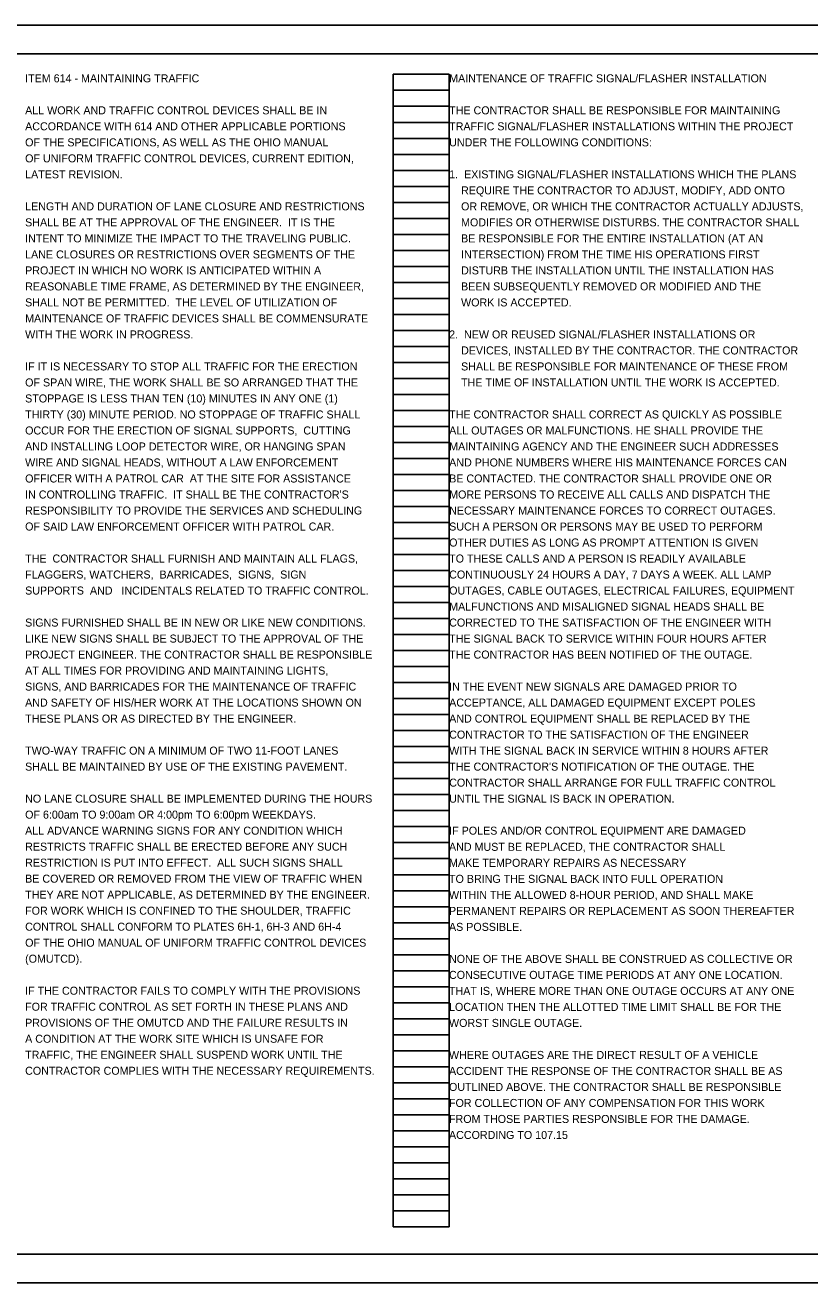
# Model space of a CAD drawing. Extents: x -7.3 to 34, y 0 to 22.
# Drawn here: x 2.4 to 16.13, y 0 to 22 of the extents above; entities that cross this region are included whole.
import ezdxf

# ---------------------------------------------------------------- set-up
doc = ezdxf.new("R2010")
doc.units = 0
for name, color, linetype in [('SH_Border', 7, 'Continuous'), ('SH_Cut_Line', 7, 'Continuous'), ('SH_Data', 7, 'Continuous'), ('SH_Text', 7, 'Continuous')]:
    doc.layers.add(name, color=color, linetype=linetype)

msp = doc.modelspace()

# ---------------------------------------------------------------- linework, layer by layer
at = {"layer": 'SH_Border'}
msp.add_lwpolyline([(1.5, 21.5), (33.5, 21.5), (33.5, 0.5), (1.5, 0.5)], close=True, dxfattribs=at)
at = {"layer": 'SH_Cut_Line'}
msp.add_lwpolyline([(0, 0), (34, 0), (34, 22), (0, 22)], close=True, dxfattribs=at)
at = {"layer": 'SH_Data'}
for p, q in [((8.84, 0.98), (8.84, 21.14)), ((8.84, 21.14), (9.82, 21.14)), ((9.82, 0.98), (9.82, 21.14)), ((8.84, 20.86), (9.82, 20.86)), ((8.84, 20.58), (9.82, 20.58)), ((8.84, 20.3), (9.82, 20.3)), ((8.84, 20.02), (9.82, 20.02)), ((8.84, 19.74), (9.82, 19.74)), ((8.84, 19.46), (9.82, 19.46)), ((8.84, 19.18), (9.82, 19.18)), ((8.84, 18.9), (9.82, 18.9)), ((8.84, 18.62), (9.82, 18.62)), ((8.84, 18.34), (9.82, 18.34)), ((8.84, 18.06), (9.82, 18.06)), ((8.84, 17.78), (9.82, 17.78)), ((8.84, 17.5), (9.82, 17.5)), ((8.84, 17.22), (9.82, 17.22)), ((8.84, 16.94), (9.82, 16.94)), ((8.84, 16.66), (9.82, 16.66)), ((8.84, 16.38), (9.82, 16.38)), ((8.84, 16.1), (9.82, 16.1)), ((8.84, 15.82), (9.82, 15.82)), ((8.84, 15.54), (9.82, 15.54)), ((8.84, 15.26), (9.82, 15.26)), ((8.84, 14.98), (9.82, 14.98)), ((8.84, 14.7), (9.82, 14.7)), ((8.84, 14.42), (9.82, 14.42)), ((8.84, 14.14), (9.82, 14.14)), ((8.84, 13.86), (9.82, 13.86)), ((8.84, 13.58), (9.82, 13.58)), ((8.84, 13.3), (9.82, 13.3)), ((8.84, 13.02), (9.82, 13.02)), ((8.84, 12.74), (9.82, 12.74)), ((8.84, 12.46), (9.82, 12.46)), ((8.84, 12.18), (9.82, 12.18)), ((8.84, 11.9), (9.82, 11.9)), ((8.84, 11.62), (9.82, 11.62)), ((8.84, 11.34), (9.82, 11.34)), ((8.84, 11.06), (9.82, 11.06)), ((8.84, 10.78), (9.82, 10.78)), ((8.84, 10.5), (9.82, 10.5)), ((8.84, 10.22), (9.82, 10.22)), ((8.84, 9.94), (9.82, 9.94)), ((8.84, 9.66), (9.82, 9.66)), ((8.84, 9.38), (9.82, 9.38)), ((8.84, 9.1), (9.82, 9.1)), ((8.84, 8.82), (9.82, 8.82)), ((8.84, 8.54), (9.82, 8.54)), ((8.84, 8.26), (9.82, 8.26)), ((8.84, 7.98), (9.82, 7.98)), ((8.84, 7.7), (9.82, 7.7)), ((8.84, 7.42), (9.82, 7.42)), ((8.84, 7.14), (9.82, 7.14)), ((8.84, 6.86), (9.82, 6.86)), ((8.84, 6.58), (9.82, 6.58)), ((8.84, 6.3), (9.82, 6.3)), ((8.84, 6.02), (9.82, 6.02)), ((8.84, 5.74), (9.82, 5.74)), ((8.84, 5.46), (9.82, 5.46)), ((8.84, 5.18), (9.82, 5.18)), ((8.84, 4.9), (9.82, 4.9)), ((8.84, 4.62), (9.82, 4.62)), ((8.84, 4.34), (9.82, 4.34)), ((8.84, 4.06), (9.82, 4.06)), ((8.84, 3.78), (9.82, 3.78)), ((8.84, 3.5), (9.82, 3.5)), ((8.84, 3.22), (9.82, 3.22)), ((8.84, 2.94), (9.82, 2.94)), ((8.84, 2.66), (9.82, 2.66)), ((8.84, 2.38), (9.82, 2.38)), ((8.84, 2.1), (9.82, 2.1)), ((8.84, 1.82), (9.82, 1.82)), ((8.84, 1.54), (9.82, 1.54)), ((8.84, 1.26), (9.82, 1.26)), ((8.84, 0.98), (9.82, 0.98))]:
    msp.add_line(p, q, dxfattribs=at)

# ---------------------------------------------------------------- texts
at = {"layer": 'SH_Text'}
for s, p in [('ITEM 614 - MAINTAINING TRAFFIC', (2.4, 21)), ('MAINTENANCE OF TRAFFIC SIGNAL/FLASHER INSTALLATION', (9.82, 21)), ('ALL WORK AND TRAFFIC CONTROL DEVICES SHALL BE IN', (2.4, 20.44)), ('THE CONTRACTOR SHALL BE RESPONSIBLE FOR MAINTAINING', (9.82, 20.44)), ('ACCORDANCE WITH 614 AND OTHER APPLICABLE PORTIONS', (2.4, 20.16)), ('TRAFFIC SIGNAL/FLASHER INSTALLATIONS WITHIN THE PROJECT', (9.82, 20.16)), ('OF THE SPECIFICATIONS, AS WELL AS THE OHIO MANUAL', (2.4, 19.88)), ('UNDER THE FOLLOWING CONDITIONS:', (9.82, 19.88)), ('OF UNIFORM TRAFFIC CONTROL DEVICES, CURRENT EDITION,', (2.4, 19.6)), ('LATEST REVISION.', (2.4, 19.32)), ('1.  EXISTING SIGNAL/FLASHER INSTALLATIONS WHICH THE PLANS', (9.82, 19.32)), ('    REQUIRE THE CONTRACTOR TO ADJUST, MODIFY, ADD ONTO', (9.82, 19.04)), ('LENGTH AND DURATION OF LANE CLOSURE AND RESTRICTIONS', (2.4, 18.76)), ('    OR REMOVE, OR WHICH THE CONTRACTOR ACTUALLY ADJUSTS,', (9.82, 18.76)), ('SHALL BE AT THE APPROVAL OF THE ENGINEER.  IT IS THE', (2.4, 18.48)), ('    MODIFIES OR OTHERWISE DISTURBS. THE CONTRACTOR SHALL', (9.82, 18.48)), ('INTENT TO MINIMIZE THE IMPACT TO THE TRAVELING PUBLIC.', (2.4, 18.2)), ('    BE RESPONSIBLE FOR THE ENTIRE INSTALLATION (AT AN', (9.82, 18.2)), ('LANE CLOSURES OR RESTRICTIONS OVER SEGMENTS OF THE', (2.4, 17.92)), ('    INTERSECTION) FROM THE TIME HIS OPERATIONS FIRST', (9.82, 17.92)), ('PROJECT IN WHICH NO WORK IS ANTICIPATED WITHIN A', (2.4, 17.64)), ('    DISTURB THE INSTALLATION UNTIL THE INSTALLATION HAS', (9.82, 17.64)), ('REASONABLE TIME FRAME, AS DETERMINED BY THE ENGINEER,', (2.4, 17.36)), ('    BEEN SUBSEQUENTLY REMOVED OR MODIFIED AND THE', (9.82, 17.36)), ('SHALL NOT BE PERMITTED.  THE LEVEL OF UTILIZATION OF', (2.4, 17.08)), ('    WORK IS ACCEPTED.', (9.82, 17.08)), ('MAINTENANCE OF TRAFFIC DEVICES SHALL BE COMMENSURATE', (2.4, 16.8)), ('WITH THE WORK IN PROGRESS.', (2.4, 16.52)), ('2.  NEW OR REUSED SIGNAL/FLASHER INSTALLATIONS OR', (9.82, 16.52)), ('    DEVICES, INSTALLED BY THE CONTRACTOR. THE CONTRACTOR', (9.82, 16.24)), ('IF IT IS NECESSARY TO STOP ALL TRAFFIC FOR THE ERECTION', (2.4, 15.96)), ('    SHALL BE RESPONSIBLE FOR MAINTENANCE OF THESE FROM', (9.82, 15.96)), ('OF SPAN WIRE, THE WORK SHALL BE SO ARRANGED THAT THE', (2.4, 15.68)), ('    THE TIME OF INSTALLATION UNTIL THE WORK IS ACCEPTED.', (9.82, 15.68)), ('STOPPAGE IS LESS THAN TEN (10) MINUTES IN ANY ONE (1)', (2.4, 15.4)), ('THIRTY (30) MINUTE PERIOD. NO STOPPAGE OF TRAFFIC SHALL', (2.4, 15.12)), ('THE CONTRACTOR SHALL CORRECT AS QUICKLY AS POSSIBLE', (9.82, 15.12)), ('OCCUR FOR THE ERECTION OF SIGNAL SUPPORTS,  CUTTING', (2.4, 14.84)), ('ALL OUTAGES OR MALFUNCTIONS. HE SHALL PROVIDE THE', (9.82, 14.84)), ('AND INSTALLING LOOP DETECTOR WIRE, OR HANGING SPAN', (2.4, 14.56)), ('MAINTAINING AGENCY AND THE ENGINEER SUCH ADDRESSES', (9.82, 14.56)), ('WIRE AND SIGNAL HEADS, WITHOUT A LAW ENFORCEMENT', (2.4, 14.28)), ('AND PHONE NUMBERS WHERE HIS MAINTENANCE FORCES CAN', (9.82, 14.28)), ('OFFICER WITH A PATROL CAR  AT THE SITE FOR ASSISTANCE', (2.4, 14)), ('BE CONTACTED. THE CONTRACTOR SHALL PROVIDE ONE OR', (9.82, 14)), ("IN CONTROLLING TRAFFIC.  IT SHALL BE THE CONTRACTOR'S", (2.4, 13.72)), ('MORE PERSONS TO RECEIVE ALL CALLS AND DISPATCH THE', (9.82, 13.72)), ('RESPONSIBILITY TO PROVIDE THE SERVICES AND SCHEDULING', (2.4, 13.44)), ('NECESSARY MAINTENANCE FORCES TO CORRECT OUTAGES.', (9.82, 13.44)), ('OF SAID LAW ENFORCEMENT OFFICER WITH PATROL CAR.', (2.4, 13.16)), ('SUCH A PERSON OR PERSONS MAY BE USED TO PERFORM', (9.82, 13.16)), ('OTHER DUTIES AS LONG AS PROMPT ATTENTION IS GIVEN', (9.82, 12.88)), ('THE  CONTRACTOR SHALL FURNISH AND MAINTAIN ALL FLAGS,', (2.4, 12.6)), ('TO THESE CALLS AND A PERSON IS READILY AVAILABLE', (9.82, 12.6)), ('FLAGGERS, WATCHERS,  BARRICADES,  SIGNS,  SIGN', (2.4, 12.32)), ('CONTINUOUSLY 24 HOURS A DAY, 7 DAYS A WEEK. ALL LAMP', (9.82, 12.32)), ('SUPPORTS  AND   INCIDENTALS RELATED TO TRAFFIC CONTROL.', (2.4, 12.04)), ('OUTAGES, CABLE OUTAGES, ELECTRICAL FAILURES, EQUIPMENT', (9.82, 12.04)), ('MALFUNCTIONS AND MISALIGNED SIGNAL HEADS SHALL BE', (9.82, 11.76)), ('SIGNS FURNISHED SHALL BE IN NEW OR LIKE NEW CONDITIONS.', (2.4, 11.48)), ('CORRECTED TO THE SATISFACTION OF THE ENGINEER WITH', (9.82, 11.48)), ('LIKE NEW SIGNS SHALL BE SUBJECT TO THE APPROVAL OF THE', (2.4, 11.2)), ('THE SIGNAL BACK TO SERVICE WITHIN FOUR HOURS AFTER', (9.82, 11.2)), ('PROJECT ENGINEER. THE CONTRACTOR SHALL BE RESPONSIBLE', (2.4, 10.92)), ('THE CONTRACTOR HAS BEEN NOTIFIED OF THE OUTAGE.', (9.82, 10.92)), ('AT ALL TIMES FOR PROVIDING AND MAINTAINING LIGHTS,', (2.4, 10.64)), ('SIGNS, AND BARRICADES FOR THE MAINTENANCE OF TRAFFIC', (2.4, 10.36)), ('IN THE EVENT NEW SIGNALS ARE DAMAGED PRIOR TO', (9.82, 10.36)), ('AND SAFETY OF HIS/HER WORK AT THE LOCATIONS SHOWN ON', (2.4, 10.08)), ('ACCEPTANCE, ALL DAMAGED EQUIPMENT EXCEPT POLES', (9.82, 10.08)), ('THESE PLANS OR AS DIRECTED BY THE ENGINEER.', (2.4, 9.8)), ('AND CONTROL EQUIPMENT SHALL BE REPLACED BY THE', (9.82, 9.8)), ('CONTRACTOR TO THE SATISFACTION OF THE ENGINEER', (9.82, 9.52)), ('TWO-WAY TRAFFIC ON A MINIMUM OF TWO 11-FOOT LANES', (2.4, 9.24)), ('WITH THE SIGNAL BACK IN SERVICE WITHIN 8 HOURS AFTER', (9.82, 9.24)), ('SHALL BE MAINTAINED BY USE OF THE EXISTING PAVEMENT.', (2.4, 8.96)), ("THE CONTRACTOR'S NOTIFICATION OF THE OUTAGE. THE", (9.82, 8.96)), ('CONTRACTOR SHALL ARRANGE FOR FULL TRAFFIC CONTROL', (9.82, 8.68)), ('NO LANE CLOSURE SHALL BE IMPLEMENTED DURING THE HOURS', (2.4, 8.4)), ('UNTIL THE SIGNAL IS BACK IN OPERATION. ', (9.82, 8.4)), ('OF 6:00am TO 9:00am OR 4:00pm TO 6:00pm WEEKDAYS.', (2.4, 8.12)), ('ALL ADVANCE WARNING SIGNS FOR ANY CONDITION WHICH', (2.4, 7.84)), ('IF POLES AND/OR CONTROL EQUIPMENT ARE DAMAGED', (9.82, 7.84)), ('RESTRICTS TRAFFIC SHALL BE ERECTED BEFORE ANY SUCH', (2.4, 7.56)), ('AND MUST BE REPLACED, THE CONTRACTOR SHALL ', (9.817, 7.557)), ('RESTRICTION IS PUT INTO EFFECT.  ALL SUCH SIGNS SHALL', (2.4, 7.28)), ('MAKE TEMPORARY REPAIRS AS NECESSARY ', (9.817, 7.277)), ('BE COVERED OR REMOVED FROM THE VIEW OF TRAFFIC WHEN', (2.4, 7)), ('TO BRING THE SIGNAL BACK INTO FULL OPERATION', (9.817, 6.997)), ('THEY ARE NOT APPLICABLE, AS DETERMINED BY THE ENGINEER.', (2.4, 6.72)), ('WITHIN THE ALLOWED 8-HOUR PERIOD, AND SHALL MAKE', (9.817, 6.717)), ('FOR WORK WHICH IS CONFINED TO THE SHOULDER, TRAFFIC', (2.4, 6.44)), ('PERMANENT REPAIRS OR REPLACEMENT AS SOON THEREAFTER', (9.817, 6.437)), ('CONTROL SHALL CONFORM TO PLATES 6H-1, 6H-3 AND 6H-4', (2.4, 6.16)), ('AS POSSIBLE.', (9.817, 6.157)), ('OF THE OHIO MANUAL OF UNIFORM TRAFFIC CONTROL DEVICES', (2.4, 5.88)), ('(OMUTCD).', (2.4, 5.6)), ('NONE OF THE ABOVE SHALL BE CONSTRUED AS COLLECTIVE OR', (9.817, 5.597)), ('CONSECUTIVE OUTAGE TIME PERIODS AT ANY ONE LOCATION.', (9.817, 5.317)), ('IF THE CONTRACTOR FAILS TO COMPLY WITH THE PROVISIONS', (2.4, 5.04)), ('THAT IS, WHERE MORE THAN ONE OUTAGE OCCURS AT ANY ONE', (9.817, 5.037)), ('FOR TRAFFIC CONTROL AS SET FORTH IN THESE PLANS AND', (2.4, 4.76)), ('LOCATION THEN THE ALLOTTED TIME LIMIT SHALL BE FOR THE', (9.817, 4.757)), ('PROVISIONS OF THE OMUTCD AND THE FAILURE RESULTS IN', (2.4, 4.48)), ('WORST SINGLE OUTAGE.', (9.817, 4.477)), ('A CONDITION AT THE WORK SITE WHICH IS UNSAFE FOR', (2.4, 4.2)), ('TRAFFIC, THE ENGINEER SHALL SUSPEND WORK UNTIL THE', (2.4, 3.92)), ('WHERE OUTAGES ARE THE DIRECT RESULT OF A VEHICLE', (9.817, 3.917)), ('CONTRACTOR COMPLIES WITH THE NECESSARY REQUIREMENTS.', (2.4, 3.64)), ('ACCIDENT THE RESPONSE OF THE CONTRACTOR SHALL BE AS', (9.817, 3.637)), ('OUTLINED ABOVE. THE CONTRACTOR SHALL BE RESPONSIBLE', (9.817, 3.357)), ('FOR COLLECTION OF ANY COMPENSATION FOR THIS WORK', (9.817, 3.077)), ('FROM THOSE PARTIES RESPONSIBLE FOR THE DAMAGE.', (9.817, 2.797)), ('ACCORDING TO 107.15', (9.817, 2.517))]:
    msp.add_text(s, height=0.14, dxfattribs=at).set_placement(p)

doc.saveas('drawing.dxf')
